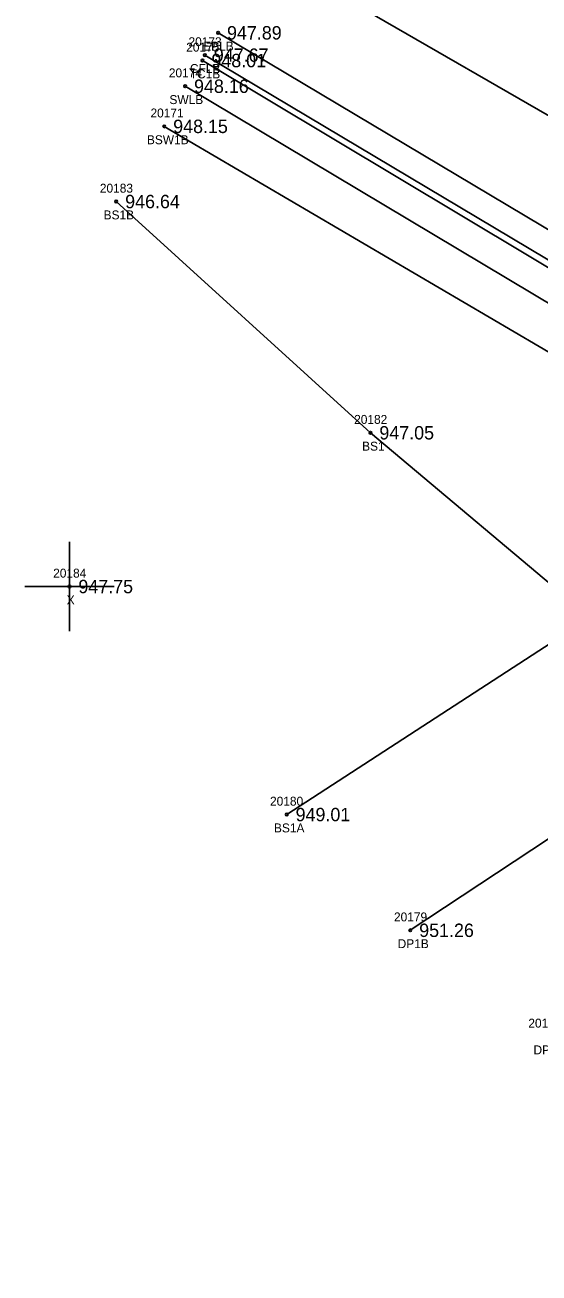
# Model space of a CAD drawing. Extents: x 1576181 to 1577685, y 1099396 to 1101490.
# Drawn here: x 1576181.3 to 1576239, y 1099603.2 to 1099743.2 of the extents above; entities that cross this region are included whole.
import ezdxf

# ---------------------------------------------------------------- set-up
doc = ezdxf.new("R2010")
doc.units = 0
for name, color, linetype in [('RD_DTM_BkLn1', 7, 'Continuous'), ('RD_DTM_BkLn2', 7, 'Continuous'), ('RD_DTM_BkLn_txCode', 7, 'Continuous'), ('RD_EX_Conc', 7, 'Continuous'), ('RD_EX_Conc_txCode', 7, 'Continuous'), ('RD_EX_Driveway', 7, 'Continuous'), ('RD_EX_Driveway_txCode', 7, 'Continuous'), ('RD_EX_Misc', 7, 'Continuous'), ('RD_EX_Misc_txCode', 7, 'Continuous'), ('RD_EX_Road', 7, 'Continuous'), ('RD_EX_Road_txCode', 7, 'Continuous'), ('RD_EX_TX_Conc_ELEV', 7, 'Continuous'), ('RD_EX_TX_Driveway_ELEV', 7, 'Continuous'), ('RD_EX_TX_Misc_ELEV', 7, 'Continuous'), ('RD_EX_TX_Road_ELEV', 7, 'Continuous'), ('RD_SMD_Locator', 7, 'Continuous')]:
    doc.layers.add(name, color=color, linetype=linetype)

msp = doc.modelspace()

# ---------------------------------------------------------------- linework, layer by layer
at = {"layer": 'RD_DTM_BkLn1'}
msp.add_lwpolyline([(1576411.06, 1099606.41), (1576377.33, 1099642.66), (1576337.77, 1099673.47), (1576295.75, 1099700.12), (1576252.73, 1099725.71), (1576209.23, 1099750.79)], dxfattribs=at)
at = {"layer": 'RD_DTM_BkLn2'}
for points in [[(1576267.66, 1099695.7), (1576269.39, 1099698.81), (1576245.1, 1099712.92), (1576201.25, 1099739.16)], [(1576210.7, 1099654.61), (1576244.76, 1099676.71), (1576220.1, 1099697.42), (1576191.57, 1099723.35)]]:
    msp.add_lwpolyline(points, dxfattribs=at)
at = {"layer": 'RD_EX_Conc'}
for points in [[(1576268.15, 1099695.41), (1576270.1, 1099699.18), (1576245.51, 1099713.56), (1576201.52, 1099739.77)], [(1576267.66, 1099695.7), (1576243.88, 1099709.67), (1576199.3, 1099736.28)], [(1576375.69, 1099614.26), (1576362.91, 1099628.6), (1576326.83, 1099655.21), (1576295.5, 1099672.67), (1576283.88, 1099680.17), (1576241.84, 1099705.44), (1576196.96, 1099731.78)]]:
    msp.add_lwpolyline(points, dxfattribs=at)
at = {"layer": 'RD_EX_Driveway'}
msp.add_lwpolyline([(1576283.88, 1099680.17), (1576267.39, 1099669.9), (1576224.57, 1099641.63)], dxfattribs=at)
at = {"layer": 'RD_EX_Misc'}
for p, q in [((1576186.32, 1099675.18), (1576186.32, 1099685.18)), ((1576181.32, 1099680.18), (1576191.32, 1099680.18))]:
    msp.add_line(p, q, dxfattribs=at)
at = {"layer": 'RD_EX_Road'}
msp.add_lwpolyline([(1576385.97, 1099603.2), (1576388.62, 1099605.88), (1576388.15, 1099611.28), (1576384.7, 1099615.46), (1576386.17, 1099616.78), (1576370.2, 1099635.03), (1576357.38, 1099647.31), (1576346.63, 1099656.32), (1576334.08, 1099664.49), (1576324.15, 1099670.38), (1576289.72, 1099690.82), (1576247.01, 1099716.05), (1576203, 1099742.27)], dxfattribs=at)
at = {"layer": 'RD_SMD_Locator'}
for centre in [(1576203, 1099742.27), (1576201.25, 1099739.16), (1576201.52, 1099739.77), (1576199.3, 1099736.28), (1576196.96, 1099731.78), (1576191.57, 1099723.35), (1576220.1, 1099697.42), (1576186.32, 1099680.18), (1576210.7, 1099654.61), (1576224.57, 1099641.63)]:
    msp.add_circle(centre, 0.15, dxfattribs=at)

# ---------------------------------------------------------------- texts
at = {"layer": 'RD_DTM_BkLn_txCode'}
for s, p in [('20183', (1576189.73, 1099724.35)), ('BS1B', (1576190.15, 1099721.35)), ('20182', (1576218.27, 1099698.42)), ('BS1', (1576219.16, 1099695.42)), ('20180', (1576208.83, 1099655.61)), ('BS1A', (1576209.27, 1099652.61))]:
    msp.add_text(s, height=1, dxfattribs=at).set_placement(p)
at = {"layer": 'RD_EX_Conc_txCode'}
for s, p in [('20175', (1576199.42, 1099740.16)), ('20173', (1576199.68, 1099740.77)), ('20174', (1576197.47, 1099737.28)), ('TC1B', (1576199.82, 1099737.16)), ('CFLB', (1576199.84, 1099737.77)), ('SWLB', (1576197.54, 1099734.28)), ('20171', (1576195.41, 1099732.78)), ('BSW1B', (1576195.01, 1099729.78))]:
    msp.add_text(s, height=1, dxfattribs=at).set_placement(p)
at = {"layer": 'RD_EX_Driveway_txCode'}
for s, p in [('20179', (1576222.74, 1099642.63)), ('DP1B', (1576223.15, 1099639.63)), ('20178', (1576237.82, 1099630.72)), ('DPB', (1576238.4, 1099627.72))]:
    msp.add_text(s, height=1, dxfattribs=at).set_placement(p)
at = {"layer": 'RD_EX_Misc_txCode'}
for s, p in [('20184', (1576184.49, 1099681.18)), ('X', (1576186.01, 1099678.18))]:
    msp.add_text(s, height=1, dxfattribs=at).set_placement(p)
at = {"layer": 'RD_EX_Road_txCode'}
msp.add_text('EPLB', height=1, dxfattribs=at).set_placement((1576201.33, 1099740.27))
at = {"layer": 'RD_EX_TX_Conc_ELEV'}
for s, p in [('948.01', (1576202.25, 1099738.41)), ('947.67', (1576202.52, 1099739.02)), ('948.16', (1576200.3, 1099735.53)), ('948.15', (1576197.96, 1099731.03))]:
    msp.add_text(s, height=1.5, dxfattribs=at).set_placement(p)
at = {"layer": 'RD_EX_TX_Driveway_ELEV'}
msp.add_text('951.26', height=1.5, dxfattribs=at).set_placement((1576225.57, 1099640.88))
at = {"layer": 'RD_EX_TX_Misc_ELEV'}
for s, p in [('946.64', (1576192.57, 1099722.6)), ('947.05', (1576221.1, 1099696.67)), ('947.75', (1576187.32, 1099679.43)), ('949.01', (1576211.7, 1099653.86))]:
    msp.add_text(s, height=1.5, dxfattribs=at).set_placement(p)
at = {"layer": 'RD_EX_TX_Road_ELEV'}
msp.add_text('947.89', height=1.5, dxfattribs=at).set_placement((1576204, 1099741.52))

doc.saveas('drawing.dxf')
